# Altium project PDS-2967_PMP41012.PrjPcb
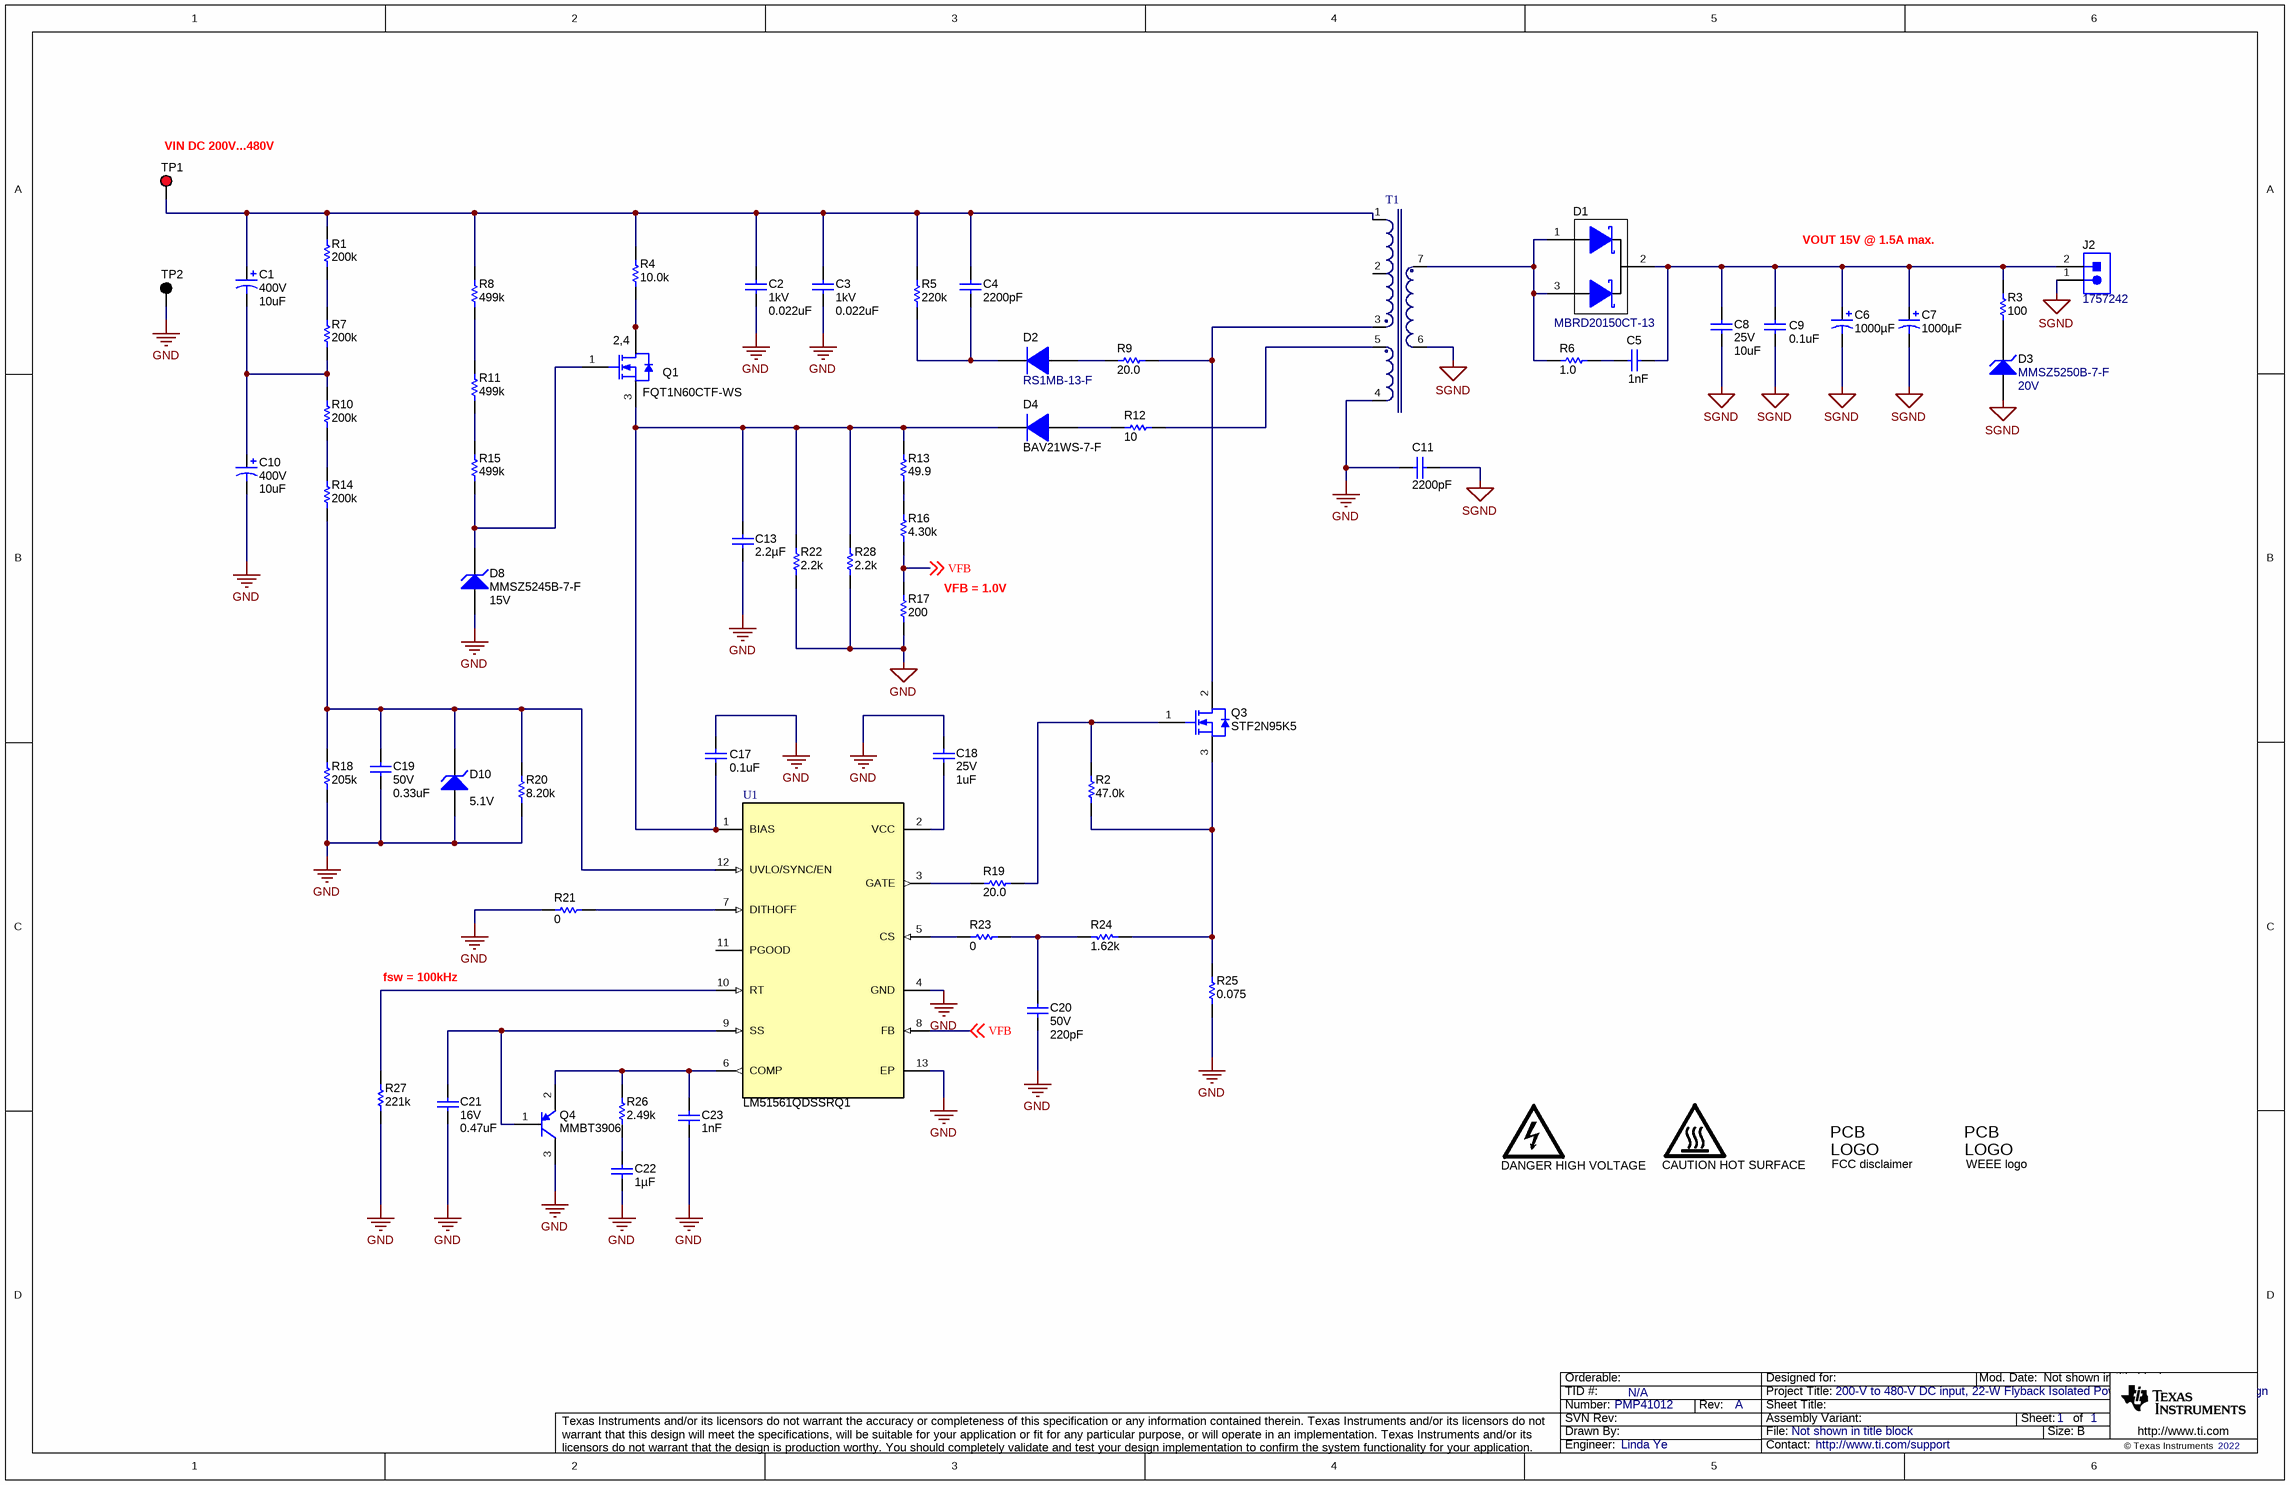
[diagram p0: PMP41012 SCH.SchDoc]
TID: N/A; TechSupport: http://www.ti.com/support; SCH_Rev: A; PRJ_Title: 200-V to 480-V DC input, 22-W Flyback Isolated Power  Supply Reference Design; PRJ_Number: PMP41012; PRJ_Engineer: Linda Ye; PCB_Rev: A; CopyrightYear: 2022
1 sheet, 65 parts. Net scope: global (net labels, ports and power ports of the same name join across sheets).
Board file: PMP41012 PCB.PcbDoc

## Sheet PMP41012 SCH.SchDoc
size 431 x 279 mm; Date: Not shown in title block; ApprovedBy: Not shown in title block; CheckedBy: Not shown in title block; Author: Not shown in title block; CompanyName: Not shown in title block; Engineer: Not shown in title block; Organization: Not shown in title block; Address1: Not shown in title block; Address2: Not shown in title block; Address3: Not shown in title block; Address4: Not shown in title block; DocumentNumber: 1; Revision: Use project parameter SCH_Rev; SheetNumber: 1; SheetTotal: 1; PageSetup: Record=PageOptions¦CenterHorizontal=True¦CenterVertical=True¦PrintScale=1.00¦XCorrection=1.00¦YCorrection=1.00¦PrintKind=0¦BorderSize=5000000¦LeftOffset=0¦BottomOffset=0¦Orientation=2¦PaperLength=1000¦PaperWidth=1000¦Scale=100¦PaperSource=15¦PrintQuality=600¦MediaType=1¦DitherType=10¦PaperKind=Letter¦PrintScaleMode=1

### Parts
C1  VDC_V: 400V  ValueDisplayed: 10uF  [B43851_1000x2000]  (hidden comment: B43851A9106M)
C2  VDC_V: 1kV  ValueDisplayed: 0.022uF  [1210_220]  (hidden comment: GRM32DR73A223KW01L)
C3  VDC_V: 1kV  ValueDisplayed: 0.022uF  [1210_220]  (hidden comment: GRM32DR73A223KW01L)
C4  ValueDisplayed: 2200pF  [1206]  (hidden comment: GRM31BR72J222KW01L)
C5  ValueDisplayed: 1nF  [0805_HV]  (hidden comment: GRM21AR72E102KW01D)
C6  ValueDisplayed: 1000µF  [FR_1000x2000]  (hidden comment: EEU-FR1E102B)
C7  ValueDisplayed: 1000µF  [FR_1000x2000]  (hidden comment: EEU-FR1E102B)
C8  VDC_V: 25V  ValueDisplayed: 10uF  [1210_220]  (hidden comment: GRM32DR71E106KA12L)
C9  ValueDisplayed: 0.1uF  [0603]  (hidden comment: GRM188R71H104KA93D)
C10  VDC_V: 400V  ValueDisplayed: 10uF  [B43851_1000x2000]  (hidden comment: B43851A9106M)
C11  ValueDisplayed: 2200pF  [AY2_950x500_Straight]  (hidden comment: AY2222M35Y5US63L7)
C13  ValueDisplayed: 2.2µF  [0805_HV]  (hidden comment: CGA4J3X7R1H225K125AB)
C17  ValueDisplayed: 0.1uF  [0603]  (hidden comment: GRM188R71H104KA93D)
C18  VDC_V: 25V  ValueDisplayed: 1uF  [0603]  (hidden comment: GRM188R71E105KA12D)
C19  VDC_V: 50V  ValueDisplayed: 0.33uF  [1206]  (hidden comment: GRM319R71H334KA01D)
C20  VDC_V: 50V  ValueDisplayed: 220pF  [0603]  (hidden comment: GRM188R71H221KA01D)
C21  VDC_V: 16V  ValueDisplayed: 0.47uF  [0603]  (hidden comment: GRM188R71C474KA88D)
C22  Cap_F: 1µF  [0603]  (hidden comment: GRM188R71A105KA61D)
C23  Cap_F: 1nF  [0603]  (hidden comment: GRM188R71H102KA01D)
D1  MBRD20150CT-13  [DPAK]
D2  RS1MB-13-F  [SMB]
D3  MMSZ5250B-7-F  value 20V  [SOD-123]
D4  BAV21WS-7-F  [SOD-323]
D8  MMSZ5245B-7-F  value 15V  [SOD-123]
D10  value 5.1V  [SOD-123]  (hidden comment: MMSZ5231B-7-F)
J2  1757242  [PHOENIX_1757242]
LOGO1  DANGER HIGH VOLTAGE  [IEC_HighVoltage_Small]  (no BOM)
LOGO2  CAUTION HOT SURFACE  [IEC_HotSurface_Small]  (no BOM)
Logo3  FCC disclaimer  [FCC_disclaimer]  (no BOM)
Logo4  WEEE logo  [WEEE_Minimum]  (no BOM)
Q1  FQT1N60CTF-WS  [SOT-223]
Q3  STF2N95K5  [TO-220_FullPAK_Offset]
Q4  MMBT3906  [SOT-23]
R1  ValueDisplayed: 200k  [1206]  (hidden comment: CRCW1206200KJNEA)
R2  ValueDisplayed: 47.0k  [0603]  (hidden comment: RC0603FR-0747KL)
R3  ValueDisplayed: 100  [1206]  (hidden comment: CRCW1206100RJNEA)
R4  ValueDisplayed: 10.0k  [1206]  (hidden comment: CRCW120610K0FKEAHP)
R5  ValueDisplayed: 220k  [PR03]  (hidden comment: PR03000202203JAC00)
R6  ValueDisplayed: 1.0  [1206]  (hidden comment: CRCW12061R00JNEA)
R7  ValueDisplayed: 200k  [1206]  (hidden comment: CRCW1206200KJNEA)
R8  ValueDisplayed: 499k  [1206]  (hidden comment: CRCW1206499KFKEA)
R9  ValueDisplayed: 20.0  [2010]  (hidden comment: CRCW201020R0FKEF)
R10  ValueDisplayed: 200k  [1206]  (hidden comment: CRCW1206200KJNEA)
R11  ValueDisplayed: 499k  [1206]  (hidden comment: CRCW1206499KFKEA)
R12  ValueDisplayed: 10  [0603]  (hidden comment: CRCW060310R0JNEA)
R13  ValueDisplayed: 49.9  [0603]  (hidden comment: CRCW060349R9FKEA)
R14  ValueDisplayed: 200k  [1206]  (hidden comment: CRCW1206200KJNEA)
R15  ValueDisplayed: 499k  [1206]  (hidden comment: CRCW1206499KFKEA)
R16  ValueDisplayed: 4.30k  [0603]  (hidden comment: RC0603FR-074K3L)
R17  ValueDisplayed: 200  [0603]  (hidden comment: CRCW0603200RFKEA)
R18  ValueDisplayed: 205k  [0603]  (hidden comment: CRCW0603205KFKEA)
R19  ValueDisplayed: 20.0  [0603]  (hidden comment: CRCW060320R0FKEA)
R20  ValueDisplayed: 8.20k  [0603]  (hidden comment: RC0603FR-078K2L)
R21  ValueDisplayed: 0  [0603]  (hidden comment: CRCW06030000Z0EA)
R22  ValueDisplayed: 2.2k  [PR02]  (hidden comment: PR02000202201JR500)
R23  ValueDisplayed: 0  [0603]  (hidden comment: CRCW06030000Z0EA)
R24  ValueDisplayed: 1.62k  [0603]  (hidden comment: CRCW06031K62FKEA)
R25  ValueDisplayed: 0.075  [1206]  (hidden comment: ERJ-8BWFR075V)
R26  ValueDisplayed: 2.49k  [0603]  (hidden comment: CRCW06032K49FKEA)
R27  ValueDisplayed: 221k  [0603]  (hidden comment: CRCW0603221KFKEA)
R28  ValueDisplayed: 2.2k  [PR02]  (hidden comment: PR02000202201JR500)
T1  070-7080  [EE20-10-6_7080]  (value not drawn)
TP1  5010  [Keystone5010]  (value not drawn)
TP2  5011  [Keystone5011]  (value not drawn)
U1  LM51561QDSSRQ1  [DSS0012C]

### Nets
GND: C2.2 C3.2 C10.2(-) C11.1 C13.2 C17.1 C18.1 C19.2 C20.2 C21.2 C22.2 C23.2 D8.2(A) D10.2(A) Q4.3(C) R17.1 R18.1 R20.1 R21.1 R22.1 R25.1 R27.1 R28.1 T1.4 TP2.1 U1.4(GND) U1.13(EP)
SGND: C6.2(-) C7.2(-) C8.2 C9.2 C11.2 D3.2(A) J2.1 T1.6
VFB: R16.1 R17.2 U1.8(FB) ; off-sheet VFB
NetC1_1: C1.1(+) C2.1 C3.1 C4.1 R1.2 R4.2 R5.1 R8.2 T1.1 TP1.1
NetC1_2: C1.2(-) C10.1(+) R7.1 R10.2
NetC4_2: C4.2 D2.1(K) R5.2
NetC5_1: C5.1 C6.1(+) C7.1(+) C8.1 C9.1 D1.2(K) J2.2 R3.2
NetC5_2: C5.2 R6.2
NetC13_1: C13.1 C17.2 D4.1(K) Q1.3(S) R13.2 R22.2 R28.2 U1.1(BIAS)
NetC18_2: C18.2 U1.2(VCC)
NetC19_1: C19.1 D10.1(K) R14.1 R18.2 R20.2 U1.12(UVLO/SYNC/EN)
NetC20_1: C20.1 R23.2 R24.2
NetC21_1: C21.1 Q4.1(B) U1.9(SS)
NetC22_1: C22.1 R26.1
NetC23_1: C23.1 Q4.2(E) R26.2 U1.6(COMP)
NetD1_1: D1.1(A) D1.3(A) R6.1 T1.7
NetD2_2: D2.2(A) R9.1
NetD3_1: D3.1(K) R3.1
NetD4_2: D4.2(A) R12.1
NetD8_1: D8.1(K) Q1.1(G) R15.1
NetQ1_2: Q1.2(D) Q1.4(D) R4.1
NetQ3_1: Q3.1(G) R2.2 R19.1
NetQ3_2: Q3.2(D) R9.2 T1.3
NetQ3_3: Q3.3(S) R2.1 R24.1 R25.2
NetR1_1: R1.1 R7.2
NetR8_1: R8.1 R11.2
NetR10_1: R10.1 R14.2
NetR11_1: R11.1 R15.2
NetR12_2: R12.2 T1.5
NetR13_1: R13.1 R16.2
NetR19_2: R19.2 U1.3(GATE)
NetR21_2: R21.2 U1.7(DITHOFF)
NetR23_1: R23.1 U1.5(CS)
NetR27_2: R27.2 U1.10(RT)

Not connected (* = marked no-connect by the designer): T1 2; U1 11(PGOOD)

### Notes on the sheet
- (near TP1) VIN DC 200V...480V
- VOUT 15V @ 1.5A max.
- VFB = 1.0V
- fsw = 100kHz

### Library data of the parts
C1 C10 = CMP-0010001-3: CAP, AL, 10 uF, 400 V, +/- 20%, 18 ohm, TH; Manufacturer: TDK; TaMin_C: -25°C; ESR_ohm: 18; Polarized: Y; SizeAreaWB_mm2: 144; Value1: 18 ohm; U/M: EA; Value: 10uF; TaMax_C: 105°C; SizeZ_mm: 22; SizeX_mm: 10; Cap_Case: 10x20mm; SizeArea_mm2: 100; CompType: Capacitor; AEC Qualified: N; Cap_F: 10µF; IRMS_A: 80mA; AEC Category: Q200
C2 C3 = CMP-0009197-2: CAP, CERM, 0.022 uF, 1000 V, +/- 10%, X7R, 1210; Manufacturer: MuRata; TaMin_C: -55°C; Polarized: N; SizeAreaWB_mm2: 14.7; Value1: Unknown; U/M: EA; TaMax_C: 125°C; SizeZ_mm: 2.2; SizeX_mm: 3.2; SizeY_mm: 2.5; Cap_Case: 1210; Value2: 1000V; SizeArea_mm2: 8; Cap_F: 22nF; AEC Category: Q200
C4 = GRM31BR72J222KW01L: CAP, CERM, 2200 pF, 630 V,+/- 10%, X7R, 1206; Manufacturer: MuRata; Polarized: N; CompType: Capacitor; Value: 2200pF; U/M: EA; Cap_F: 0.0000000022; Tolerance_%: 10; VDC_V: 630; Value2: 630V; TaMin_C: -55; TaMax_C: 125; SizeArea_mm2: 5.12; SizeAreaWB_mm2: 10.92; SizeX_mm: 3.2; SizeY_mm: 1.6; SizeZ_mm: 1.35; AEC Category: Q200; Green_Lifecycle: Not Set; Green_REACh: Incomplete
C5 = CMP-0008251-2: CAP, CERM, 1000 pF, 250 V, +/- 10%, X7R, 0805; Manufacturer: MuRata; TaMin_C: -55°C; Polarized: N; SizeAreaWB_mm2: 6.75; Value1: Unknown; U/M: EA; Value: 1000pF; TaMax_C: 125°C; SizeZ_mm: 1.45; SizeX_mm: 2; SizeY_mm: 1.25; Cap_Case: 0805; Value2: 250V; SizeArea_mm2: 2.5; AEC Category: Q200
C6 C7 = EEU-FR1E102B: CAP, AL, 1000 µF, 25 V, +/- 20%, 0.02 ohm, TH; Manufacturer: Panasonic; Polarized: Y; CompType: Capacitor; Value: 1000uF; U/M: EA; Cap_F: 0.001; Tolerance_%: 20; VDC_V: 25; Value2: 25V; ESR_ohm: 0.02; IRMS_A: 2.18; TaMin_C: -40; TaMax_C: 105; Cap_Case: 10x20; SizeAreaWB_mm2: 144; SizeArea_mm2: 100; SizeX_mm: 10; SizeZ_mm: 22; AEC Category: Q200; AEC Qualified: N
C8 = CMP-0009190-2: CAP, CERM, 10 uF, 25 V, +/- 10%, X7R, 1210; Manufacturer: MuRata; TaMin_C: -55°C; Polarized: N; SizeAreaWB_mm2: 14.7; Value1: Unknown; U/M: EA; Value: 10uF; TaMax_C: 125°C; SizeZ_mm: 2.2; SizeX_mm: 3.2; SizeY_mm: 2.5; Cap_Case: 1210; SizeArea_mm2: 8; Cap_F: 10µF; AEC Category: Q200
C9 C17 = CMP-0007434-4: CAP, CERM, 0.1 uF, 50 V, +/- 10%, X7R, 0603; Manufacturer: MuRata; TaMin_C: -55°C; Polarized: N; SizeAreaWB_mm2: 4.68; Value1: Unknown; U/M: EA; Value: 0.1uF; TaMax_C: 125°C; SizeZ_mm: 1; SizeX_mm: 1.6; SizeY_mm: 0.8; Value2: 50V; SizeArea_mm2: 1.28; Cap_F: 100nF; AEC Category: Q200
C11 = AY2222M35Y5US63L7: CAP, CERM, 2200 pF, X1 440 VAC/Y2 300 VAC, +/- 20%, Y5U, AEC-Q200 Grade 1, D9.5xT5mm; Manufacturer: Vishay-Bccomponents; Polarized: N; CompType: Capacitor; Value: 2200pF; U/M: EA; Cap_F: 0.0000000022; Tolerance_%: 20; TaMin_C: -55; TaMax_C: 125; Cap_Case: 9.5x5mm; SizeArea_mm2: 47.5; SizeAreaWB_mm2: 80.5; SizeX_mm: 9.5; SizeY_mm: 5; SizeZ_mm: 14.5; AEC Category: Q200; AEC Qualified: Y; AEC Grade: 1; AC_Safety: X1Y2; VAC_X: 440; VAC_Y: 300
C13 = CGA4J3X7R1H225K125AB: CAP, CERM, 2.2 µF, 50 V,+/- 10%, X7R, AEC-Q200 Grade 1, 0805; Manufacturer: TDK; Polarized: N; CompType: Capacitor; Value: 2.2uF; U/M: EA; Cap_F: 0.0000022; Tolerance_%: 10; ESR_ohm: 0.003288; Value1: 0.003288 ohm; VDC_V: 50; Value2: 50V; IRMS_A: 3.60029; TaMin_C: -55; TaMax_C: 125; Cap_Case: 0805; SizeArea_mm2: 2.5; SizeAreaWB_mm2: 6.75; SizeX_mm: 2; SizeY_mm: 1.25; SizeZ_mm: 1.45; AEC Category: Q200; AEC Qualified: Y; AEC Grade: 1
C18 = CMP-0007405-4: CAP, CERM, 1 uF, 25 V, +/- 10%, X7R, 0603; Manufacturer: MuRata; TaMin_C: -55°C; Polarized: N; SizeAreaWB_mm2: 4.68; Value1: Unknown; U/M: EA; Value: 1uF; TaMax_C: 125°C; SizeZ_mm: 1; SizeX_mm: 1.6; SizeY_mm: 0.8; SizeArea_mm2: 1.28; Cap_F: 1µF; AEC Category: Q200
C19 = CMP-0008880-2: CAP, CERM, 0.33 uF, 50 V, +/- 10%, X7R, 1206; Manufacturer: MuRata; TaMin_C: -55°C; Polarized: N; SizeAreaWB_mm2: 10.92; Value1: Unknown; U/M: EA; Value: 0.33uF; TaMax_C: 125°C; SizeZ_mm: 1.35; SizeX_mm: 3.2; SizeY_mm: 1.6; SizeArea_mm2: 5.12; Cap_F: 330nF; AEC Category: Q200
C20 = CMP-0007442-5: CAP, CERM, 220 pF, 50 V, +/- 10%, X7R, 0603; Manufacturer: MuRata; TaMin_C: -55°C; Polarized: N; SizeAreaWB_mm2: 4.68; Value1: Unknown; U/M: EA; Value: 220pF; TaMax_C: 125°C; SizeZ_mm: 1; SizeX_mm: 1.6; SizeY_mm: 0.8; SizeArea_mm2: 1.28; AEC Category: Q200
C21 = CMP-0007398-4: CAP, CERM, 0.47 uF, 16 V, +/- 10%, X7R, 0603; Manufacturer: MuRata; TaMin_C: -55°C; Polarized: N; SizeAreaWB_mm2: 4.68; Value1: Unknown; U/M: EA; Value: 0.47uF; TaMax_C: 125°C; SizeZ_mm: 1; SizeX_mm: 1.6; SizeY_mm: 0.8; SizeArea_mm2: 1.28; Cap_F: 470nF; AEC Category: Q200
C22 = CMP-0007365-4: CAP, CERM, 1 uF, 10 V, +/- 10%, X7R, 0603; Manufacturer: MuRata; TaMin_C: -55°C; ESR_ohm: 0.011; Polarized: N; SizeAreaWB_mm2: 4.68; Value1: 0.011 ohm; U/M: EA; Value: 1uF; TaMax_C: 125°C; SizeZ_mm: 1; SizeX_mm: 1.6; SizeY_mm: 0.8; Value2: 10V; SizeArea_mm2: 1.28; AEC Category: Q200
C23 = CMP-0007432-3: CAP, CERM, 1000 pF, 50 V, +/- 10%, X7R, 0603; Manufacturer: MuRata; TaMin_C: -55°C; Polarized: N; SizeAreaWB_mm2: 4.68; Value1: Unknown; U/M: EA; Value: 1000pF; TaMax_C: 125°C; SizeZ_mm: 1; SizeX_mm: 1.6; SizeY_mm: 0.8; Value2: 50V; SizeArea_mm2: 1.28; AEC Category: Q200
D1 = CMP-0028958-2: Diode, Schottky, 150 V, 10 A, DPAK; Manufacturer: Diodes Inc.; SizeY_mm: 6.54; Value1: 10A; Vr_V: 150V; SizeAreaWB_mm2: 101.7114; SizeX_mm: 9.91; TJmax_C: 175°C; AEC Qualified: N; Value2: 0.9V; SizeArea_mm2: 64.8114; AEC Category: Q101; U/M: EA; Value: 150V; Vf_V: 900mV; SizeZ_mm: 2.29; Green_Lifecycle: Not Set; Green_REACh: Incomplete
D2 = CMP-0076889-1: Diode, P-N, 1000 V, 1 A, SMB; Manufacturer: Diodes Inc.; SizeAreaWB_mm2: 44.156; Vr_V: 1kV; SizeArea_mm2: 21.336; TJmax_C: 150°C; AEC Category: Q101; Value: 1000V; SizeZ_mm: 2.6; Green_REACh: Passed; Io_A: 1A; Vf_V: 1.3V; SizeY_mm: 3.81; Green_Lifecycle: Active; U/M: EA; SizeX_mm: 5.6; RJC_CperW: 20.0
D3 = CMP-0005756-4: Diode, Zener, 20 V, 500 mW, SOD-123; Manufacturer: Diodes Inc.; SizeX_mm: 3.85; AEC Category: Q101; SizeY_mm: 1.7; Power_W: 500mW; SizeZ_mm: 1.35; SizeAreaWB_mm2: 13.095; RJA_CperW: 350; Value1: 0.5W; SizeArea_mm2: 6.545
D4 = CMP-0029165-2: Diode, Switching, 250 V, 0.25 A, AEC-Q101, SOD-323; Manufacturer: Diodes Inc.; Green_Lifecycle: Active; Io_A: 250mA; SizeZ_mm: 1; Green_REACh: Passed; AEC Qualified: Y; SizeAreaWB_mm2: 8.695; SizeX_mm: 2.7; Value1: 0.25A; Value: 250V; Vf_V: 1.25V; SizeArea_mm2: 3.645; AEC Category: Q101; TJmax_C: 150°C; SizeY_mm: 1.35
D8 = CMP-0005753-2: Diode, Zener, 15 V, 500 mW, SOD-123; Manufacturer: Diodes Inc.; Power_W: 500mW; SizeAreaWB_mm2: 13.095; Value1: 0.5W; RJA_CperW: 350; U/M: EA; SizeZ_mm: 1.35; SizeX_mm: 3.85; SizeY_mm: 1.7; SizeArea_mm2: 6.545; AEC Category: Q101
D10 = CMP-0005802-1: Diode, Zener, 5.1 V, 500 mW, SOD-123; Manufacturer: Diodes Inc.; Power_W: 500mW; SizeAreaWB_mm2: 13.095; Value1: 0.5W; RJA_CperW: 350; U/M: EA; SizeZ_mm: 1.35; SizeX_mm: 3.85; SizeY_mm: 1.7; SizeArea_mm2: 6.545; AEC Category: Q101
J2 = CMP-0055534-1: Header (Shrouded), 5.08 mm, 2x1, Tin, R/A, TH; Manufacturer: Phoenix Contact; CT: FALSE
LOGO1 = CMP-0074835-1: IEC 61010-1 High Voltage Warning; Library Reference: IEC_HighVoltage; SymbolCreator: a0412235
LOGO2 = CMP-0074837-1: IEC 61010-1 Hot Surface Warning; Library Reference: IEC_HotSurface; SymbolCreator: a0412235
Logo3 = CMP-0074847-1: FCC_disclaimer; Library Reference: Logo
Logo4 = CMP-0074769-1
Q1 = CMP-0081663-1: MOSFET, N-CH, 600 V, SOT-223; Manufacturer: Infineon; Alternate Manufacturer: None; ChType: N; SizeAreaWB_mm2: 76.5; SizeArea_mm2: 45.5; VdsMax_V: 800V; Vgs_V: 20V; Value: 600V; SizeZ_mm: 1.6; SizeY_mm: 7; Value2: ? nC; Value1: ? ohm; SizeX_mm: 6.5
Q3 = CMP-0001279-3: MOSFET, N-CH, 800 V, 9 A, TO-220FP; PartNumber: STF10N80K5; Alternate Manufacturer: None; Manufacturer: STMicroelectronics; RevisionId: 1; AccessRights: 2147483647; Folder: Unified Components\Transistors\MOSFET\N-Channel\VDS 200 V+\; ContentType: Component; SizeZ_mm: 20; ChType: N; Value2: 22 nC; VdsMax_V: 800V; SizeX_mm: 10.2; SizeY_mm: 4.5; Vgs_V: 30V; QgTyp_nC: 22; Value: 800V; SizeArea_mm2: 45.9; AEC Category: Q101; IdsMax_A: 9A; SizeAreaWB_mm2: 79.3; U/M: EA
Q4 = CMP-0000325-2: Transistor, PNP, 40 V, 0.2 A, SOT-23; Manufacturer: Fairchild Semiconductor; TaMax_C: 150°C; Value2: 300; Value1: 0.2 A; Vcesat1_V: 2.5dV; SizeX_mm: 2.5; SizeY_mm: 3; TaMin_C: -55°C; IcRated_A: 2dA; CompType: BJT; SizeZ_mm: 1.1; Value: 40 V; SizeArea_mm2: 7.5; NPN: 0; Vceo_V: 40V; PNP: 1; AEC Category: Q101; SizeAreaWB_mm2: 14; U/M: EA
R1 R7 R10 R14 = CMP-0018624-3: RES, 200 k, 5%, 0.25 W, AEC-Q200 Grade 0, 1206; Manufacturer: Vishay-Dale; Power_W: 250mW; TempCo: 200 ppm/C; Value: 200k; EIA_Code: E24; SizeX_mm: 3.2; SizeY_mm: 1.6; SizeZ_mm: 1.35; Value2: 0.25W; SizeArea_mm2: 5.12; AEC Qualified: Y; VDC_V: 200V; AEC Category: Q200; AEC Grade: 0
R2 = CMP-0023133-2: RES, 47.0 k, 1%, 0.1 W, 0603; Manufacturer: Yageo America; Power_W: 100mW; TempCo: 200 ppm/C; Value_Code: 47k0; U/M: EA; Value: 47.0k; Res_ohm: 47k; SizeX_mm: 1.6; SizeY_mm: 0.8; SizeZ_mm: 1; Value2: 0.1W; SizeArea_mm2: 1.28; VDC_V: 150V; AEC Category: Q200
R3 = CMP-0018575-3: RES, 100, 5%, 0.25 W, AEC-Q200 Grade 0, 1206; Manufacturer: Vishay-Dale; Power_W: 250mW; TempCo: 200 ppm/C; Value_Code: 100R; Value: 100; EIA_Code: E24; SizeX_mm: 3.2; SizeY_mm: 1.6; SizeZ_mm: 1.35; Value2: 0.25W; SizeArea_mm2: 5.12; AEC Qualified: Y; VDC_V: 200V; AEC Category: Q200; AEC Grade: 0
R4 = CMP-0016578-3: RES, 10.0 k, 1%, 0.5 W, AEC-Q200 Grade 0, 1206; Manufacturer: Vishay-Dale; Power_W: 500mW; TempCo: 100 ppm/C; Value_Code: 10k0; Value: 10.0k; EIA_Code: E96; Res_ohm: 10k; SizeX_mm: 3.2; SizeY_mm: 1.6; SizeZ_mm: 1.35; Value2: 0.5W; SizeArea_mm2: 5.12; AEC Qualified: Y; AEC Category: Q200; AEC Grade: 0
R5 = PR03000202203JAC00: RES, 220 k, 5%, 3 W, D5.20xL16.70mm; Manufacturer: Vishay-Bccomponents; CompType: Resistor; Value: 220k; Res_ohm: 220000; Tolerance_%: 5; Power_W: 3; Value2: 3W; VDC_V: 750; TempCo: 250 ppm/C; EIA_Code: E24; U/M: EA; AEC Category: Q200; AEC Qualified: N
R6 = CMP-0018617-2: RES, 1.0, 5%, 0.25 W, 1206; Manufacturer: Vishay-Dale; Power_W: 250mW; TempCo: 200 ppm/C; Value_Code: 1R00; U/M: EA; Value: 1.0; EIA_Code: E24; Res_ohm: 1; SizeX_mm: 3.2; SizeY_mm: 1.6; SizeZ_mm: 1.35; Value2: 0.25W; SizeArea_mm2: 5.12; VDC_V: 200V; AEC Category: Q200
R8 R11 R15 = CMP-0017016-3: RES, 499 k, 1%, 0.25 W, AEC-Q200 Grade 0, 1206; Manufacturer: Vishay-Dale; Power_W: 250mW; TempCo: 100 ppm/C; Value: 499k; EIA_Code: E96; SizeX_mm: 3.2; SizeY_mm: 1.6; SizeZ_mm: 1.35; Value2: 0.25W; SizeArea_mm2: 5.12; AEC Qualified: Y; VDC_V: 200V; AEC Category: Q200; AEC Grade: 0
R9 = CMP-0016307-3: RES, 20.0, 1%, 0.75 W, AEC-Q200 Grade 0, 2010; Manufacturer: Vishay-Dale; Power_W: 750mW; TempCo: 100 ppm/C; Value_Code: 20R0; Value: 20.0; EIA_Code: E96; Res_ohm: 20; SizeX_mm: 5; SizeY_mm: 2.5; SizeZ_mm: 1.66; Value2: 0.75W; SizeArea_mm2: 12.5; AEC Qualified: Y; VDC_V: 400V; AEC Grade: 0; AEC Category: Q200
R12 = CMP-0025703-1: RES, 10, 5%, 0.1 W, 0603; Manufacturer: Vishay-Dale; Power_W: 100mW; TempCo: 200 ppm/C; Value_Code: 10R0; U/M: EA; Value: 10; EIA_Code: E24; SizeX_mm: 1.6; SizeY_mm: 0.8; SizeZ_mm: 1; Value2: 0.1W; SizeArea_mm2: 1.28; VDC_V: 75V; AEC Category: Q200
R13 = CMP-0022448-4: RES, 49.9, 1%, 0.1 W, AEC-Q200 Grade 0, 0603; Manufacturer: Vishay-Dale; Power_W: 100mW; TempCo: 100 ppm/C; Value_Code: 49R9; Value: 49.9; EIA_Code: E96; SizeX_mm: 1.6; SizeY_mm: 0.8; SizeZ_mm: 1; Value2: 0.1W; SizeArea_mm2: 1.28; AEC Qualified: Y; VDC_V: 75V; AEC Category: Q200; AEC Grade: 0
R16 = RC0603FR-074K3L: RES, 4.30 k, 1%, 0.1 W, 0603; Manufacturer: Yageo America; CompType: Resistor; Value: 4.30k; Res_ohm: 4300; Value_Code: 4k30; Tolerance_%: 1; Power_W: 0.1; Value2: 0.1W; VDC_V: 150; TempCo: 200 ppm/C; SizeArea_mm2: 1.28; SizeX_mm: 1.6; SizeY_mm: 0.8; U/M: EA; AEC Category: Q200
R17 = CMP-0022201-5: RES, 200, 1%, 0.1 W, AEC-Q200 Grade 0, 0603; Manufacturer: Vishay-Dale; Power_W: 100mW; TempCo: 100 ppm/C; Value_Code: 200R; Value: 200; EIA_Code: E96; SizeX_mm: 1.6; SizeY_mm: 0.8; SizeZ_mm: 1; Value2: 0.1W; SizeArea_mm2: 1.28; AEC Qualified: Y; VDC_V: 75V; AEC Category: Q200; AEC Grade: 0
R18 = CMP-0022202-4: RES, 205 k, 1%, 0.1 W, AEC-Q200 Grade 0, 0603; Manufacturer: Vishay-Dale; Power_W: 100mW; TempCo: 100 ppm/C; Value: 205k; EIA_Code: E96; SizeX_mm: 1.6; SizeY_mm: 0.8; SizeZ_mm: 1; Value2: 0.1W; SizeArea_mm2: 1.28; AEC Qualified: Y; VDC_V: 75V; AEC Category: Q200; AEC Grade: 0
R19 = CMP-0022206-3: RES, 20.0, 1%, 0.1 W, 0603; Manufacturer: Vishay-Dale; Power_W: 100mW; TempCo: 100 ppm/C; Value_Code: 20R0; U/M: EA; Value: 20.0; EIA_Code: E96; Res_ohm: 20; SizeX_mm: 1.6; SizeY_mm: 0.8; SizeZ_mm: 1; Value2: 0.1W; SizeArea_mm2: 1.28; VDC_V: 75V; AEC Category: Q200
R20 = RC0603FR-078K2L: RES, 8.20 k, 1%, 0.1 W, 0603; Manufacturer: Yageo America; CompType: Resistor; Value: 8.20k; Res_ohm: 8200; Value_Code: 8k20; Tolerance_%: 1; Power_W: 0.1; Value2: 0.1W; VDC_V: 150; TempCo: 200 ppm/C; SizeArea_mm2: 1.28; SizeX_mm: 1.6; SizeY_mm: 0.8; U/M: EA; AEC Category: Q200; Green_Lifecycle: Active; Green_REACh: Passed
R21 R23 = CMP-0025697-4: RES, 0, 5%, 0.1 W, AEC-Q200 Grade 0, 0603; Manufacturer: Vishay-Dale; Power_W: 100mW; TempCo: 200 ppm/C; Value_Code: 0000; Value: 0; EIA_Code: E24; SizeX_mm: 1.6; SizeY_mm: 0.8; SizeZ_mm: 1; Value2: 0.1W; SizeArea_mm2: 1.28; AEC Qualified: Y; VDC_V: 75V; AEC Category: Q200
R22 R28 = PR02000202201JR500: RES, 2.2 k, 5%, 2 W, AEC-Q200 Grade 0, Axial resistor; Manufacturer: Vishay-Bccomponents; Value: 2.2k; Res_ohm: 2200; Value_Code: 2k20; Tolerance_%: 5; Power_W: 2; Value2: 2W; VDC_V: 500; TempCo: 250 ppm/C; EIA_Code: E24; U/M: EA; AEC Category: Q200; AEC Qualified: Y; AEC Grade: 0
R24 = CMP-0022129-4: RES, 1.62 k, 1%, 0.1 W, AEC-Q200 Grade 0, 0603; Manufacturer: Vishay-Dale; Power_W: 100mW; TempCo: 100 ppm/C; Value_Code: 1k62; Value: 1.62k; EIA_Code: E96; SizeX_mm: 1.6; SizeY_mm: 0.8; SizeZ_mm: 1; Value2: 0.1W; SizeArea_mm2: 1.28; AEC Qualified: Y; VDC_V: 75V; AEC Category: Q200; AEC Grade: 0
R25 = ERJ-8BWFR075V: RES, 0.075, 1%, 0.5 W, 1206; Manufacturer: Panasonic; CompType: Resistor; Value: 0.075; Value_Code: R075; Tolerance_%: 1; Power_W: 0.5; Value2: 0.5W; VDC_V: 0; TempCo: 150 ppm/C; SizeArea_mm2: 5.12; SizeX_mm: 3.2; SizeY_mm: 1.6; SizeZ_mm: 1.35; EIA_Code: E96; U/M: EA; AEC Category: Q200
R26 = CMP-0022277-4: RES, 2.49 k, 1%, 0.1 W, AEC-Q200 Grade 0, 0603; Manufacturer: Vishay-Dale; Power_W: 100mW; TempCo: 100 ppm/C; Value_Code: 2k49; Value: 2.49k; EIA_Code: E96; SizeX_mm: 1.6; SizeY_mm: 0.8; SizeZ_mm: 1; Value2: 0.1W; SizeArea_mm2: 1.28; AEC Qualified: Y; VDC_V: 75V; AEC Category: Q200; AEC Grade: 0
R27 = CMP-0022216-4: RES, 221 k, 1%, 0.1 W, AEC-Q200 Grade 0, 0603; Manufacturer: Vishay-Dale; Power_W: 100mW; TempCo: 100 ppm/C; Value: 221k; EIA_Code: E96; SizeX_mm: 1.6; SizeY_mm: 0.8; SizeZ_mm: 1; Value2: 0.1W; SizeArea_mm2: 1.28; AEC Qualified: Y; VDC_V: 75V; AEC Category: Q200; AEC Grade: 0
T1 = EE20/10/6 (EF20), 070-7080: EE20/10/6 (EF20) 14-Term. EXT, THT, Horizontal; Manufacturer: Würth Elektronik Midcom; Core: 150-1945
TP1 = CMP-0055147-1: Test Point, Multipurpose, Red, TH; Manufacturer: Keystone; CNHeader: FALSE; Green_Lifecycle: Active; Green_REACh: Passed; ContactFinish: Silver; CT: TRUE
TP2 = CMP-0055148-1: Test Point, Multipurpose, Black, TH; Manufacturer: Keystone; CNHeader: FALSE; Green_Lifecycle: Active; Green_REACh: Passed; ContactFinish: Silver; CT: TRUE
U1 = CMP-0860749-1: 2.2-MHz Wide VIN 65-V Non-synchronous Boost/SEPIC/Flyback Controller with Dual Random Spread Spectrum, DSS0012C (WSON-12); Alternate Manufacturer: Texas Instruments; Alternate PartNumber: LM51561QDSSTQ1; SizeArea_mm2: 6; SizeY_mm: 3; CompType: IC; AEC Category: Q200; AEC Qualified: Y; SizeAreaWB_mm2: 12; SizeZ_mm: 0.8; SizeX_mm: 2

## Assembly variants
001: not fitted C2 C3 C5 R6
